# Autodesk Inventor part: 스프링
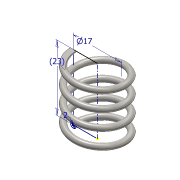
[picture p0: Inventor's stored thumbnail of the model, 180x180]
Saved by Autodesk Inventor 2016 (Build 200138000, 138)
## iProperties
Created: 2017-07
Part Number: 스프링
Material: 스테인레스 스틸
Document SubType Name: Modeling
Designer: KSEW
Mass: 5.27004 g
Surface Area: 13.4118 cm^2
Volume: 0.658755 cm^3
Density: 8 g/cm^3
Appearance: 반연마
Author: KSEW
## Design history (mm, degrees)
sketch "스케치1"
  geometry: L1 (0, 23)-(8.5, 23); L2 (8.5, 23)-(8.5, 0); L3 (8.5, 0)-(0, 0); L4 (0, 0)-(0, 23); C1 r 1 at (8.5, 0); 1 further point
  constraints: 8 end point, 2 coincident, 2 parallel, 1 centre point, 1 horizontal, 1 perpendicular
  dimensions: "d0" = 17 diameter of L2 L4; "d1" = 23 distance of L1.end L2.end (derived); "d2" = 2 diameter of C1
feature "코일1" pitch "d3" = 10; turns "d5" = 4; dims "d4" = 23 (= d1), "d6" = 0, angle "d7" = 90 deg, angle "d8" = 90 deg, "d9" = 0, "d10" = 0
sketch "스케치2"
  geometry: L1 (-7.5, 0)-(-9.5, 0) reference; 1 further point
  constraints: 1 horizontal alignment
extrude "돌출1" cut sketch "스케치2" stored distance "d11" = 10; taper "d12" = 0 deg
node "작업 평면1"
sketch "스케치3"
  geometry: L1 (7.5, 0)-(9.5, 0) reference; 1 further point
  constraints: 1 horizontal alignment
extrude "돌출2" cut sketch "스케치3" stored distance "d14" = 10; taper "d15" = 0 deg
node "솔리드1"
node "절단 모서리 투영1"
node "절단 모서리 투영2"
other parameters: "d13" = 90 deg
